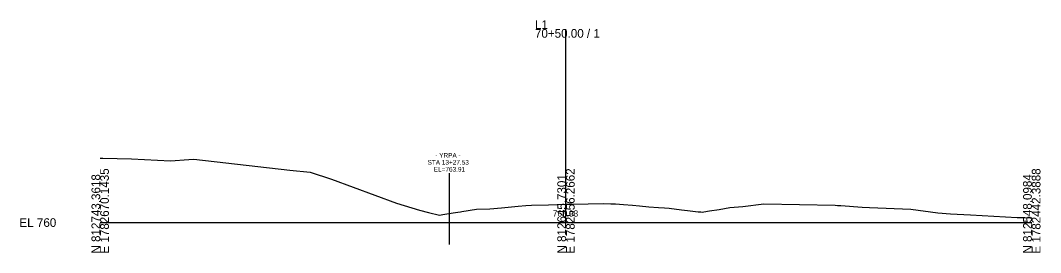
# Model space of a CAD drawing. Extents: x 5574 to 10203, y -10 to 9546.
# Drawn here: x 7574.3 to 7902.8, y 7990.3 to 8065.2 of the extents above; entities that cross this region are included whole.
import ezdxf

# ---------------------------------------------------------------- set-up
doc = ezdxf.new("R2010")
doc.units = 0
for name, color, linetype in [('Exist Cross Section Cell', 7, 'Continuous'), ('Exist XS Center Line Elevation Label', 7, 'Continuous'), ('Exist XS Ground Line', 7, 'Continuous'), ('Prop XS Vertical Lines Alignments', 7, 'Continuous')]:
    doc.layers.add(name, color=color, linetype=linetype)

msp = doc.modelspace()

# ---------------------------------------------------------------- linework, layer by layer
at = {"layer": 'Exist Cross Section Cell'}
for p, q in [((7750, 8000), (7750, 8062.41)), ((7600, 8000), (7750, 8000)), ((7750, 8000), (7900, 8000))]:
    msp.add_line(p, q, dxfattribs=at)
at = {"layer": 'Exist XS Ground Line'}
for p, q in [((7600, 8020.8), (7600.88, 8020.77)), ((7600.88, 8020.77), (7610.08, 8020.57)), ((7610.08, 8020.57), (7622.67, 8019.88)), ((7622.67, 8019.88), (7628.53, 8020.37)), ((7628.53, 8020.37), (7630.12, 8020.4)), ((7630.12, 8020.4), (7661.05, 8016.88)), ((7661.05, 8016.88), (7667.63, 8016.28)), ((7667.63, 8016.28), (7674.52, 8013.98)), ((7674.52, 8013.98), (7695.37, 8006.31)), ((7695.37, 8006.31), (7702.83, 8003.98)), ((7702.83, 8003.98), (7705.73, 8003.23)), ((7705.73, 8003.23), (7709.26, 8002.42)), ((7710.3, 8002.58), (7713.7, 8003.13)), ((7713.7, 8003.13), (7715.22, 8003.38)), ((7715.22, 8003.38), (7716.03, 8003.43)), ((7716.03, 8003.43), (7716.48, 8003.57)), ((7716.48, 8003.57), (7721.22, 8004.29)), ((7721.22, 8004.29), (7725.48, 8004.45)), ((7725.48, 8004.45), (7729.28, 8004.71)), ((7729.28, 8004.71), (7734.63, 8005.33)), ((7734.63, 8005.33), (7737.04, 8005.49)), ((7737.04, 8005.49), (7738.87, 8005.6)), ((7738.87, 8005.6), (7744.36, 8005.76)), ((7744.36, 8005.76), (7750, 8005.93)), ((7750, 8005.93), (7751.45, 8005.97)), ((7751.45, 8005.97), (7757.15, 8006.08)), ((7757.15, 8006.08), (7762.24, 8006.18)), ((7762.24, 8006.18), (7764.48, 8006.09)), ((7764.48, 8006.09), (7765.99, 8006.03)), ((7765.99, 8006.03), (7768.47, 8005.87)), ((7768.47, 8005.87), (7771.46, 8005.61)), ((7771.46, 8005.61), (7773.7, 8005.37)), ((7773.7, 8005.37), (7776.65, 8005.11)), ((7776.65, 8005.11), (7779.82, 8004.9)), ((7779.82, 8004.9), (7781.74, 8004.78)), ((7781.74, 8004.78), (7783.27, 8004.62)), ((7783.27, 8004.62), (7787.22, 8004.16)), ((7787.22, 8004.16), (7789.16, 8003.93)), ((7789.16, 8003.93), (7792.52, 8003.46)), ((7792.52, 8003.46), (7793.06, 8003.48)), ((7793.06, 8003.48), (7793.43, 8003.41)), ((7793.43, 8003.41), (7793.87, 8003.38)), ((7793.87, 8003.38), (7794.36, 8003.46)), ((7794.36, 8003.46), (7796.25, 8003.8)), ((7796.25, 8003.8), (7799.33, 8004.23)), ((7799.33, 8004.23), (7802.77, 8004.87)), ((7802.77, 8004.87), (7807, 8005.15)), ((7807, 8005.15), (7813.7, 8006.09)), ((7813.7, 8006.09), (7836.66, 8005.57)), ((7836.66, 8005.57), (7837.47, 8005.54)), ((7837.47, 8005.54), (7838.55, 8005.46)), ((7838.55, 8005.46), (7845.42, 8004.98)), ((7845.42, 8004.98), (7847.7, 8004.86)), ((7847.7, 8004.86), (7861.07, 8004.3)), ((7861.07, 8004.3), (7869.7, 8003.11)), ((7869.7, 8003.11), (7873.8, 8002.85)), ((7709.26, 8002.42), (7710.3, 8002.58)), ((7873.8, 8002.85), (7880.24, 8002.47)), ((7880.24, 8002.47), (7895.34, 8001.68)), ((7895.34, 8001.68), (7897.8, 8001.62)), ((7897.8, 8001.62), (7899.5, 8001.51)), ((7899.5, 8001.51), (7900, 8001.48))]:
    msp.add_line(p, q, dxfattribs=at)
at = {"layer": 'Prop XS Vertical Lines Alignments'}
msp.add_line((7712.34, 8015.93), (7712.34, 7992.91), dxfattribs=at)

# ---------------------------------------------------------------- texts
at = {"layer": 'Exist Cross Section Cell'}
for s, p in [('70+50.00 / 1', (7740, 8059.61)), ('L1', (7740, 8062.41)), ('EL 760', (7574, 7998.6))]:
    msp.add_text(s, height=2.8, dxfattribs=at).set_placement(p)
for s, p in [('E 1782670.1435', (7602.8, 7990)), ('E 1782556.2662', (7752.8, 7990)), ('E 1782442.3888', (7902.8, 7990)), ('N 812743.3618', (7600, 7990)), ('N 812645.7301', (7750, 7990)), ('N 812548.0984', (7900, 7990))]:
    msp.add_text(s, height=2.8, rotation=90, dxfattribs=at).set_placement(p)
at = {"layer": 'Exist XS Center Line Elevation Label'}
msp.add_text('765.93', height=2, dxfattribs=at).set_placement((7745.75, 8001.93))
at = {"layer": 'Prop XS Vertical Lines Alignments'}
for s, p in [('STA 13+27.53', (7705.42, 8018.68)), ('- YRPA -', (7707.91, 8020.93)), ('EL=763.91', (7707.43, 8016.43))]:
    msp.add_text(s, height=1.5, dxfattribs=at).set_placement(p)

doc.saveas('drawing.dxf')
